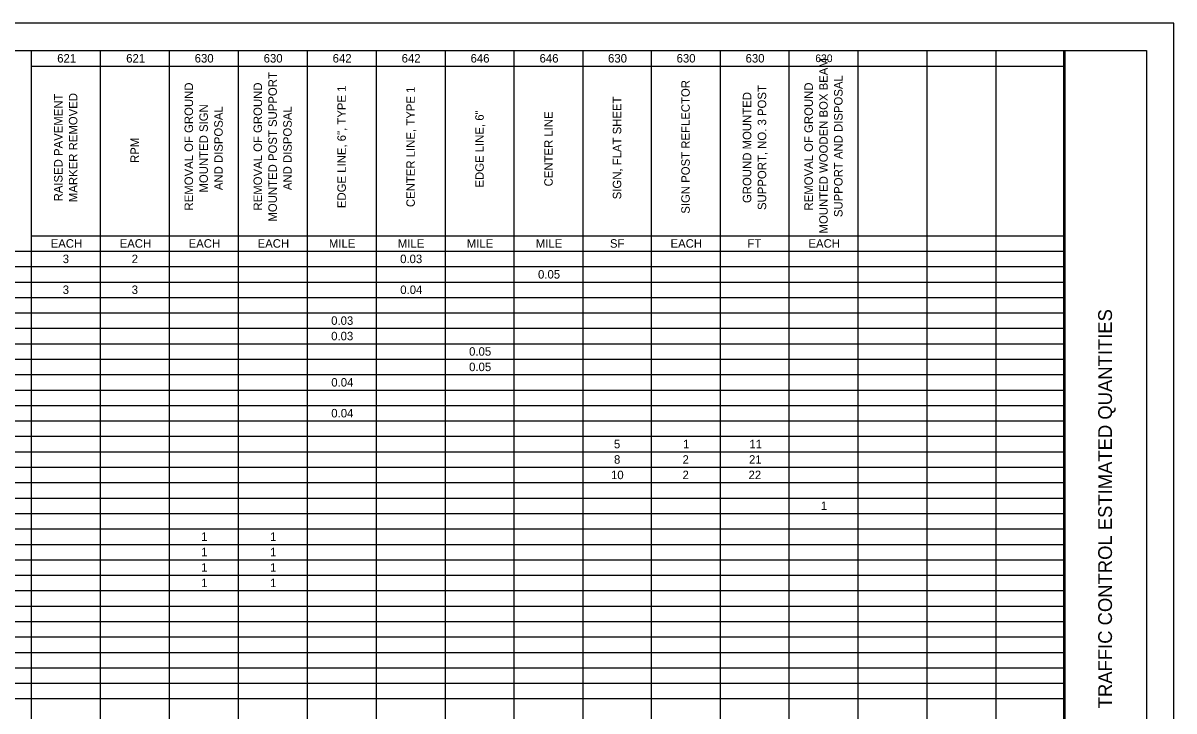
# Model space of a CAD drawing. Extents: x 0 to 34, y 0 to 22.
# Drawn here: x 13.11 to 34, y 9.52 to 22 of the extents above; entities that cross this region are included whole.
import ezdxf

# ---------------------------------------------------------------- set-up
doc = ezdxf.new("R2010")
doc.units = 0
for name, color, linetype in [('SH_Border', 7, 'Continuous'), ('SH_Cut_Line', 7, 'Continuous'), ('SH_Data', 7, 'Continuous'), ('SH_Text', 7, 'Continuous')]:
    doc.layers.add(name, color=color, linetype=linetype)

msp = doc.modelspace()

# ---------------------------------------------------------------- linework, layer by layer
at = {"layer": 'SH_Border'}
msp.add_line((32, 0.5), (32, 21.5), dxfattribs=at)
msp.add_lwpolyline([(1.5, 21.5), (33.5, 21.5), (33.5, 0.5), (1.5, 0.5)], close=True, dxfattribs=at)
at = {"layer": 'SH_Cut_Line'}
msp.add_lwpolyline([(0, 0), (34, 0), (34, 22), (0, 22)], close=True, dxfattribs=at)
at = {"layer": 'SH_Data'}
for p, q in [((1.5, 21.5), (32.02, 21.5)), ((13.26, 21.5), (13.26, 0.5)), ((14.512, 21.5), (14.512, 0.5)), ((15.764, 21.5), (15.764, 0.5)), ((17.015, 21.5), (17.015, 0.5)), ((18.267, 21.5), (18.267, 0.5)), ((19.519, 21.5), (19.519, 0.5)), ((20.771, 21.5), (20.771, 0.5)), ((22.022, 21.5), (22.022, 0.5)), ((23.274, 21.5), (23.274, 0.5)), ((24.509, 21.5), (24.509, 0.5)), ((25.761, 21.5), (25.761, 0.5)), ((27.013, 21.5), (27.013, 0.5)), ((28.265, 21.5), (28.265, 0.5)), ((29.516, 21.5), (29.516, 0.5)), ((30.768, 21.5), (30.768, 0.5)), ((32.02, 21.5), (32.02, 0.5)), ((13.26, 21.22), (32.02, 21.22)), ((13.26, 18.14), (32.02, 18.14)), ((1.5, 17.86), (32.02, 17.86)), ((1.5, 17.58), (32.02, 17.58)), ((1.5, 17.3), (32.02, 17.3)), ((1.5, 17.02), (32.02, 17.02)), ((1.5, 16.74), (32.02, 16.74)), ((1.5, 16.46), (32.02, 16.46)), ((1.5, 16.18), (32.02, 16.18)), ((1.5, 15.9), (32.02, 15.9)), ((1.5, 15.62), (32.02, 15.62)), ((1.5, 15.34), (32.02, 15.34)), ((1.5, 15.06), (32.02, 15.06)), ((1.5, 14.78), (32.02, 14.78)), ((1.5, 14.5), (32.02, 14.5)), ((1.5, 14.22), (32.02, 14.22)), ((1.5, 13.94), (32.02, 13.94)), ((1.5, 13.66), (32.02, 13.66)), ((1.5, 13.38), (32.02, 13.38)), ((1.5, 13.1), (32.02, 13.1)), ((1.5, 12.82), (32.02, 12.82)), ((1.5, 12.54), (32.02, 12.54)), ((1.5, 12.26), (32.02, 12.26)), ((1.5, 11.98), (32.02, 11.98)), ((1.5, 11.7), (32.02, 11.7)), ((1.5, 11.42), (32.02, 11.42)), ((1.5, 11.14), (32.02, 11.14)), ((1.5, 10.86), (32.02, 10.86)), ((1.5, 10.58), (32.02, 10.58)), ((1.5, 10.3), (32.02, 10.3)), ((1.5, 10.02), (32.02, 10.02)), ((1.5, 9.74), (32.02, 9.74))]:
    msp.add_line(p, q, dxfattribs=at)

# ---------------------------------------------------------------- texts
msp.add_text('TRAFFIC CONTROL ESTIMATED QUANTITIES', height=0.25, rotation=90, dxfattribs=at).set_placement((32.875, 9.565))
at = {"layer": 'SH_Text'}
for s, height, p in [('621', 0.154, (13.732, 21.283)), ('621', 0.154, (14.984, 21.283)), ('630', 0.154, (16.227, 21.283)), ('630', 0.154, (17.479, 21.283)), ('642', 0.154, (18.731, 21.283)), ('642', 0.154, (19.983, 21.283)), ('646', 0.154, (21.234, 21.283)), ('646', 0.154, (22.486, 21.283)), ('630', 0.154, (23.729, 21.283)), ('630', 0.154, (24.973, 21.283)), ('630', 0.154, (26.225, 21.283)), ('630', 0.14, (27.491, 21.29)), ('EACH', 0.154, (13.613, 17.923)), ('EACH', 0.154, (14.865, 17.923)), ('EACH', 0.154, (16.117, 17.923)), ('EACH', 0.154, (17.369, 17.923)), ('MILE', 0.154, (18.663, 17.923)), ('MILE', 0.154, (19.914, 17.923)), ('MILE', 0.154, (21.166, 17.923)), ('MILE', 0.154, (22.418, 17.923)), ('SF', 0.154, (23.763, 17.923)), ('EACH', 0.154, (24.863, 17.923)), ('FT', 0.154, (26.259, 17.923)), ('EACH', 0.154, (27.366, 17.923)), ('3', 0.154, (13.832, 17.643)), ('2', 0.154, (15.083, 17.643)), ('0.03', 0.154, (19.956, 17.643)), ('0.05', 0.154, (22.458, 17.363)), ('3', 0.154, (13.832, 17.083)), ('3', 0.154, (15.084, 17.083)), ('0.04', 0.154, (19.958, 17.083)), ('0.03', 0.154, (18.704, 16.523)), ('0.03', 0.154, (18.704, 16.243)), ('0.05', 0.154, (21.207, 15.963)), ('0.05', 0.154, (21.207, 15.683)), ('0.04', 0.154, (18.706, 15.403)), ('0.04', 0.154, (18.706, 14.843)), ('5', 0.154, (23.836, 14.283)), ('1', 0.154, (25.089, 14.283)), ('11', 0.154, (26.294, 14.283)), ('8', 0.154, (23.837, 14.003)), ('2', 0.154, (25.081, 14.003)), ('21', 0.154, (26.287, 14.003)), ('10', 0.154, (23.783, 13.723)), ('2', 0.154, (25.081, 13.723)), ('22', 0.154, (26.279, 13.723)), ('1', 0.154, (27.592, 13.163)), ('1', 0.154, (16.343, 12.603)), ('1', 0.154, (17.595, 12.603)), ('1', 0.154, (16.343, 12.323)), ('1', 0.154, (17.595, 12.323)), ('1', 0.154, (16.343, 12.043)), ('1', 0.154, (17.595, 12.043)), ('1', 0.154, (16.343, 11.763)), ('1', 0.154, (17.595, 11.763))]:
    msp.add_text(s, height=height, dxfattribs=at).set_placement(p)
for s, p in [('MOUNTED WOODEN BOX BEAM ', (27.716, 18.181)), ('MOUNTED POST SUPPORT', (17.718, 18.397)), ('REMOVAL OF GROUND ', (16.197, 18.598)), ('REMOVAL OF GROUND ', (17.449, 18.598)), ('SIGN POST REFLECTOR', (25.212, 18.54)), ('REMOVAL OF GROUND ', (27.446, 18.598)), ('SUPPORT AND DISPOSAL', (27.985, 18.478)), ('RAISED PAVEMENT ', (13.828, 18.763)), ('MARKER REMOVED', (14.098, 18.75)), ('EDGE LINE, 6", TYPE 1', (18.97, 18.641)), ('CENTER LINE, TYPE 1', (20.222, 18.66)), ('GROUND MOUNTED ', (26.329, 18.734)), ('SUPPORT, NO. 3 POST', (26.599, 18.607)), ('MOUNTED SIGN ', (16.466, 18.924)), ('AND DISPOSAL', (16.736, 18.967)), ('AND DISPOSAL', (17.988, 18.967)), ('SIGN, FLAT SHEET', (23.969, 18.801)), ('EDGE LINE, 6"', (21.473, 19.014)), ('CENTER LINE', (22.725, 19.035)), ('RPM', (15.215, 19.461))]:
    msp.add_text(s, height=0.154, rotation=90, dxfattribs=at).set_placement(p)

doc.saveas('drawing.dxf')
